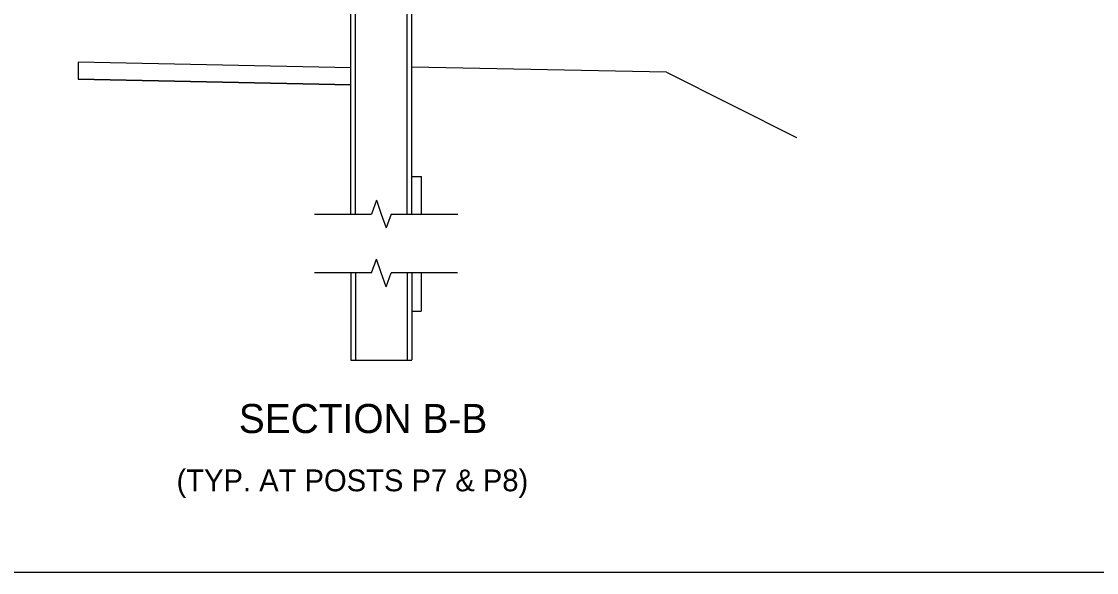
# Model space of a CAD drawing. Extents: x 49991.4 to 50021, y 49987.6 to 50011.4.
# Drawn here: x 50004.991 to 50007.949, y 49987.799 to 49989.313 of the extents above; entities that cross this region are included whole.
import ezdxf

# ---------------------------------------------------------------- set-up
doc = ezdxf.new("R2010")
doc.units = 0
for name, color, linetype in [('Level 1', 7, 'Continuous'), ('Level 2', 7, 'Continuous'), ('Level 6', 7, 'Continuous')]:
    doc.layers.add(name, color=color, linetype=linetype)

msp = doc.modelspace()

# ---------------------------------------------------------------- linework, layer by layer
at = {"layer": 'Level 1'}
for p, q in [((50005.8976, 49988.7839), (50005.8976, 49990.5649)), ((50005.9099, 49988.7839), (50005.9099, 49990.5649)), ((50006.0527, 49988.7839), (50006.0527, 49990.5649)), ((50006.0648, 49988.7839), (50006.0648, 49990.5649)), ((50005.8976, 49989.1864), (50005.1476, 49989.2014)), ((50005.8976, 49989.1395), (50005.8976, 49989.1864)), ((50006.7657, 49989.1738), (50006.0648, 49989.1878)), ((50006.7657, 49989.1738), (50007.1234, 49988.9949)), ((50005.1476, 49989.1545), (50005.8976, 49989.1395)), ((50005.8976, 49989.1395), (50005.1476, 49989.1545)), ((50006.0648, 49988.8875), (50006.0916, 49988.8875)), ((50006.0916, 49988.7839), (50006.0916, 49988.8875)), ((50005.8976, 49988.6223), (50005.8976, 49988.382)), ((50005.9099, 49988.6223), (50005.9099, 49988.382)), ((50006.0527, 49988.6223), (50006.0527, 49988.3834)), ((50006.0648, 49988.6223), (50006.0648, 49988.3834)), ((50006.0912, 49988.6223), (50006.0912, 49988.5167)), ((50006.0648, 49988.5167), (50006.0912, 49988.5167)), ((50005.8976, 49988.382), (50006.0648, 49988.382))]:
    msp.add_line(p, q, dxfattribs=at)
msp.add_lwpolyline([(49999.3835, 49998.9992), (50016.7501, 49998.9992), (50016.7501, 49987.7988), (49999.3835, 49987.7988)], close=True, dxfattribs=at)
msp.add_lwpolyline([(50005.1476, 49989.2014), (50005.1476, 49989.1545)], dxfattribs=at)
at = {"layer": 'Level 6'}
for p, q in [((50005.9678, 49988.8218), (50005.9544, 49988.7839)), ((50005.9678, 49988.8218), (50005.9812, 49988.7839)), ((50005.7976, 49988.7839), (50005.9544, 49988.7839)), ((50005.9812, 49988.7839), (50005.9947, 49988.746)), ((50006.0081, 49988.7839), (50005.9947, 49988.746)), ((50006.0081, 49988.7839), (50006.1916, 49988.7839)), ((50005.9543, 49988.6223), (50005.9677, 49988.6602)), ((50005.9812, 49988.6223), (50005.9677, 49988.6602)), ((50005.9543, 49988.6223), (50005.7976, 49988.6223)), ((50005.9946, 49988.5844), (50005.9812, 49988.6223)), ((50005.9946, 49988.5844), (50006.008, 49988.6223)), ((50006.1912, 49988.6223), (50006.008, 49988.6223))]:
    msp.add_line(p, q, dxfattribs=at)

# ---------------------------------------------------------------- texts
at = {"layer": 'Level 2'}
for s, height, p in [('SECTION B-B', 0.08, (50005.5892, 49988.182)), ('(TYP. AT POSTS P7 & P8)', 0.06, (50005.4179, 49988.022))]:
    msp.add_text(s, height=height, dxfattribs=at).set_placement(p)

doc.saveas('drawing.dxf')
